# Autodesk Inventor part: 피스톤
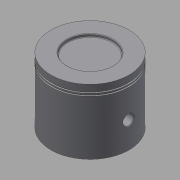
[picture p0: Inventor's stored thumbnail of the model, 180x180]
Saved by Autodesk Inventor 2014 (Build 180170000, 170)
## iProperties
Created: 2016-11
Part Number: 피스톤
Material: 강철, 탄소
Document SubType Name: Modeling
Designer: mduedu
Density: 7.87 g/cm^3
Mass: 410.128 g
Surface Area: 237.507 cm^2
Volume: 52.1129 cm^3
Appearance: 기본값
Author: mduedu
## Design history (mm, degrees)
sketch "스케치1"
  geometry: C1 r 30 at (0, 0); 1 further point
  constraints: 1 centre point, 1 coincident
  dimensions: "d0" = 60 diameter of C1
extrude "돌출1" new body sketch "스케치1" distance "d1" = 50; taper "d2" = 0 deg
sketch "스케치2"
  geometry: C1 r 28 at (0, 0); 1 further point
  constraints: 1 centre point, 1 coincident
  dimensions: "d3" = 56 diameter of C1
extrude "돌출2" cut sketch "스케치2" distance "d4" = 45; taper "d5" = 0 deg
sketch "스케치3"
  geometry: L1 (30, 0)-(30, 50) reference; L2 (30, 45)-(29, 45); L3 (29, 45)-(29, 44); L4 (29, 44)-(30, 44); L5 (30, 44)-(30, 45); L6 (30, 43)-(29, 43); L7 (29, 43)-(29, 42); L8 (29, 42)-(30, 42); L9 (30, 42)-(30, 43); L10 (30, 50)-(-30, 50) reference; L11 (0, 50)-(0, 0)
  constraints: 18 end point, 4 parallel, 3 equal length, 3 perpendicular, 2 horizontal, 2 point on line, 1 midpoint
  dimensions: "d6" = 1 distance of L2.start L2.end; "d8" = 5 distance between parallel lines of L10 L2; "d9" = 1 distance between parallel lines of L6 L4
revolve "회전1" sketch "스케치3" stored, may be unused: angle "d10" = 90 deg
node "작업 평면1"
sketch "스케치4"
  geometry: L1 (0, -22.978)-(45, -22.978) reference; L2 (45, -22.978)-(45, 22.978) reference; L3 (45, 22.978)-(0, 22.978) reference; L4 (0, 22.978)-(0, 25.377) reference; L5 (0, 25.377)-(42, 25.377) reference; L6 (42, 25.377)-(42, 24.187) reference; L7 (42, 24.187)-(43, 24.187) reference; L8 (43, 24.187)-(43, 25.377) reference; L9 (43, 25.377)-(44, 25.377) reference; L10 (44, 25.377)-(44, 24.187) reference; L11 (44, 24.187)-(45, 24.187) reference; L12 (45, 24.187)-(45, 25.377) reference; L13 (45, 25.377)-(50, 25.377) reference; L14 (50, 25.377)-(50, -25.377) reference; L15 (50, -25.377)-(45, -25.377) reference; L16 (45, -25.377)-(45, -24.187) reference; L17 (45, -24.187)-(44, -24.187) reference; L18 (44, -24.187)-(44, -25.377) reference; L19 (44, -25.377)-(43, -25.377) reference; L20 (43, -25.377)-(43, -24.187) reference; L21 (43, -24.187)-(42, -24.187) reference; L22 (42, -24.187)-(42, -25.377) reference; L23 (42, -25.377)-(0, -25.377) reference; L24 (0, -25.377)-(0, -22.978) reference; L25 (12.5, 22.978)-(45, 22.978); L26 (45, 22.978)-(45, -22.978); L27 (45, -22.978)-(12.5, -22.978); L28 (12.5, -22.978)-(12.5, 22.978); C1 r 7.5 at (20, 0); C2 r 4 at (20, 0); 1 further point
  constraints: 8 end point, 2 centre point, 2 parallel, 1 coincident, 1 horizontal, 1 horizontal alignment, 1 perpendicular, 1 point on line, 1 tangent
  dimensions: "d12" = 15 diameter of C1; "d13" = 8 diameter of C2; "d14" = 20 distance of point (0, 0) C1.centre
  node "절단 모서리 투영1"
extrude "돌출3" join sketch "스케치4" stored distance "d15" = 11.75; taper "d16" = 0 deg
extrude "돌출4" cut sketch "스케치4" stored distance "d17" = 72; taper "d18" = 0 deg
fillet "모깎기2" dims "d20" = 3
chamfer "모따기1" distance "d21" = 0.5; stored, may be unused: second distance "d22" = 2, angle "d23" = 45 deg
chamfer "모따기2" distance "d24" = 0.5; stored, may be unused: second distance "d25" = 2, angle "d26" = 45 deg
sketch "스케치5"
  geometry: C1 r 17.5 at (0, 0); 1 further point
  constraints: 1 centre point, 1 coincident
  dimensions: "d27" = 35 diameter of C1
extrude "돌출5" cut sketch "스케치5" distance "d28" = 2; taper "d29" = 0 deg
fillet "모깎기3" dims "d30" = 0.5
node "솔리드1"
mirror "대칭1"
other parameters: "d11" = -16
